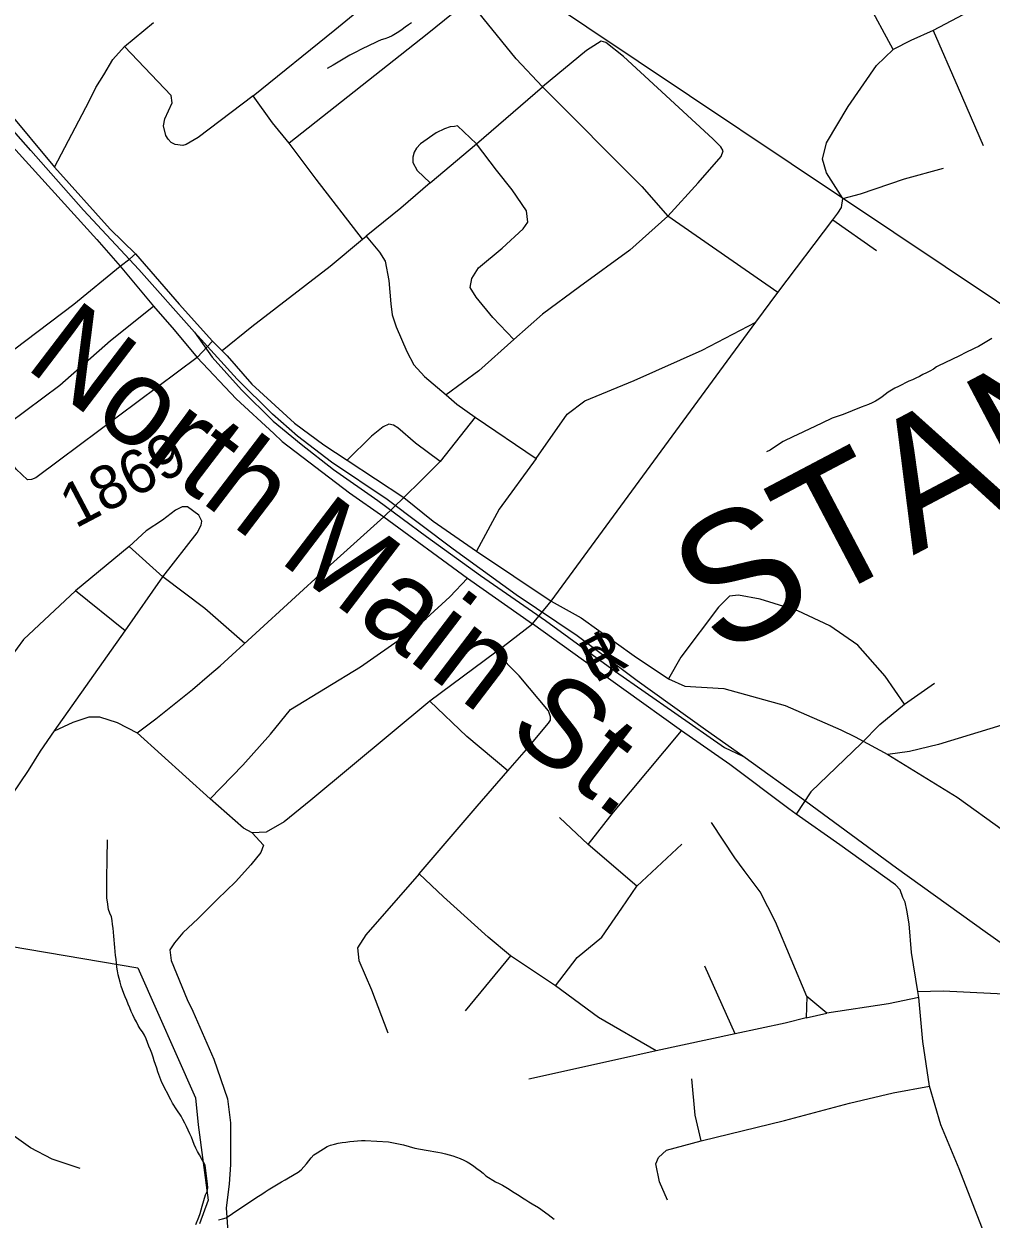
# Model space of a CAD drawing. Extents: x 1379448 to 1382868, y 593769 to 596827.
# Drawn here: x 1379666.4 to 1379829.3, y 595296.5 to 595497.8 of the extents above; entities that cross this region are included whole.
import ezdxf

# ---------------------------------------------------------------- set-up
doc = ezdxf.new("R2010")
doc.units = 0
for name, color, linetype in [('Old_Level_11', 7, 'Continuous'), ('Old_Level_29', 7, 'Continuous'), ('Old_Level_32', 7, 'Continuous'), ('Old_Level_35', 7, 'Continuous'), ('Old_Level_44', 7, 'Continuous'), ('Old_Level_48', 7, 'Continuous'), ('Old_Level_49', 7, 'Continuous'), ('Old_Level_62', 7, 'Continuous'), ('Old_Level_8', 7, 'Continuous'), ('Old_Level_9', 7, 'Continuous')]:
    doc.layers.add(name, color=color, linetype=linetype)

msp = doc.modelspace()

# ---------------------------------------------------------------- linework, layer by layer
at = {"layer": 'Old_Level_29'}
for p, q in [((1379753.4, 595398.34), (1379755.24, 595400.56)), ((1379752.06, 595396.73), (1379753.4, 595398.34))]:
    msp.add_line(p, q, dxfattribs=at)
for points in [[(1379640.12, 595529.74), (1379642.72, 595520.77), (1379644.96, 595513.08), (1379647.86, 595504.89), (1379654.08, 595493.55), (1379657.74, 595488.96), (1379663.5, 595483.3), (1379671.56, 595473.65)], [(1379671.56, 595473.65), (1379680.9, 595463.24), (1379685.19, 595459.06), (1379692.56, 595450.57), (1379698.13, 595444.33)], [(1379698.13, 595444.33), (1379700.64, 595441.89), (1379704.77, 595437.1), (1379711.95, 595430.52), (1379716.9, 595426.9), (1379720.82, 595424.32), (1379730.39, 595418.01)], [(1379730.39, 595418.01), (1379735.33, 595414.03), (1379742.61, 595408.99), (1379755.24, 595400.56)], [(1379755.24, 595400.56), (1379760.29, 595397.73), (1379769.18, 595391.34), (1379774.97, 595387.44), (1379777.73, 595386.22), (1379784.32, 595385.81), (1379794.62, 595382.96), (1379804.03, 595378.87), (1379806.45, 595377.67), (1379811.94, 595374.69)], [(1379831.52, 595285.14), (1379828.82, 595291.86), (1379827.76, 595295.11), (1379823.94, 595304.93), (1379820.88, 595312.34), (1379818.98, 595318.82), (1379817.85, 595326.38), (1379817.16, 595333.81), (1379817.01, 595334.82), (1379815.94, 595341.38), (1379815.54, 595346.18), (1379815.14, 595348.48), (1379814.85, 595349.85), (1379814.48, 595350.64), (1379813.99, 595351.9), (1379813.2, 595352.79), (1379803.84, 595359.48), (1379796.47, 595364.69), (1379795.25, 595365.55), (1379785.33, 595373.02), (1379777.19, 595378.71), (1379767.45, 595385.65), (1379752.06, 595396.73)], [(1379811.94, 595374.69), (1379823.59, 595367.52), (1379831.41, 595361.9), (1379838.57, 595356.89), (1379842.83, 595353.5), (1379846.88, 595350.52)]]:
    msp.add_lwpolyline(points, dxfattribs=at)
at = {"layer": 'Old_Level_32'}
for p, q in [((1379695.58, 595441.57), (1379698.13, 595444.33)), ((1379727, 595414.78), (1379730.39, 595418.01))]:
    msp.add_line(p, q, dxfattribs=at)
for points in [[(1379860.35, 595537.12), (1379859.21, 595532.1), (1379857.66, 595529.56), (1379852.97, 595521.73), (1379848.78, 595515.26), (1379847.74, 595513.74), (1379845.88, 595511.74), (1379840.23, 595507.84), (1379835.65, 595505.19), (1379819.59, 595496.7)], [(1379812.86, 595493.5), (1379808.42, 595501.66), (1379803.01, 595512.18)], [(1379671.56, 595473.65), (1379677.38, 595484.79), (1379678.48, 595487.05), (1379679.86, 595489.23), (1379681.35, 595491.78), (1379683.35, 595493.98), (1379688.24, 595498.01)], [(1379819.59, 595496.7), (1379815.8, 595494.97), (1379812.86, 595493.5)], [(1379819.59, 595496.7), (1379823.78, 595487.01), (1379827.98, 595477.32)], [(1379601.44, 595458.83), (1379604.66, 595459.48), (1379610.03, 595460.12), (1379613.93, 595460.7), (1379617.23, 595461.19), (1379619.97, 595462.11), (1379621.96, 595463.26), (1379624.23, 595464.88), (1379629.84, 595468.77), (1379636.24, 595473.41), (1379638.96, 595475.22), (1379642.2, 595477.66), (1379651.08, 595484.15), (1379653.96, 595485.47), (1379655.18, 595485.62), (1379656.4, 595485.42), (1379657.84, 595484.23), (1379663.4, 595478.33), (1379678.65, 595461.45), (1379682.59, 595456.98), (1379688.21, 595450.22), (1379691.72, 595446.24), (1379695.58, 595441.57)], [(1379695.58, 595441.57), (1379702.14, 595434.61), (1379708.47, 595428.8), (1379709.87, 595427.45), (1379721.23, 595418.78), (1379727, 595414.78)], [(1379647.93, 595344.33), (1379662.96, 595365.77), (1379667.13, 595372.04), (1379669.18, 595375.3), (1379671.51, 595378.71), (1379674.67, 595380.16), (1379677.4, 595381.04), (1379679.14, 595381.04), (1379682.08, 595380.13), (1379685.44, 595378.39), (1379688.63, 595380.74), (1379694.77, 595385.64), (1379697.63, 595388.12), (1379699.45, 595389.64), (1379717.45, 595406.15), (1379727, 595414.78)], [(1379727, 595414.78), (1379741.1, 595404.4), (1379752.06, 595396.73)], [(1379873.86, 595392.77), (1379845.53, 595383.99), (1379837.78, 595381.7), (1379820.5, 595376.43), (1379815.6, 595375.21), (1379811.94, 595374.69)], [(1379704.81, 595361.51), (1379706.75, 595359.44), (1379706.27, 595358.2), (1379704.61, 595356.13), (1379702.04, 595353.29), (1379698.98, 595350.35), (1379695.76, 595347.1), (1379693.13, 595344.66), (1379691.75, 595343.01), (1379690.99, 595341.84), (1379691.21, 595339.99), (1379693.86, 595333.44), (1379694.82, 595331.48), (1379698.35, 595323.42), (1379700.68, 595316.74), (1379701.17, 595312.69), (1379701.21, 595305.64), (1379700.95, 595302.32), (1379700.43, 595298.37), (1379700.82, 595293.55)]]:
    msp.add_lwpolyline(points, dxfattribs=at)
at = {"layer": 'Old_Level_35'}
for p, q in [((1379742.66, 595477.56), (1379753.75, 595487.17)), ((1379734.8, 595471.03), (1379742.66, 595477.56)), ((1379793.39, 595452.52), (1379774.85, 595465.41)), ((1379793.39, 595452.52), (1379802.68, 595464.81)), ((1379802.68, 595464.81), (1379810, 595459.63)), ((1379723.45, 595461.55), (1379724.06, 595462.06)), ((1379789.71, 595447.53), (1379793.39, 595452.52)), ((1379742.41, 595431.54), (1379736.49, 595424.09)), ((1379742.41, 595431.54), (1379752.66, 595424.59)), ((1379684.09, 595409.76), (1379675.08, 595402.29)), ((1379689.79, 595404.67), (1379684.09, 595409.76)), ((1379683.42, 595395.55), (1379689.79, 595404.67)), ((1379683.42, 595395.55), (1379675.08, 595402.29)), ((1379671.51, 595378.71), (1379683.42, 595395.55)), ((1379745.88, 595391.93), (1379752.06, 595396.73)), ((1379745.88, 595391.93), (1379734.79, 595383.69)), ((1379814.77, 595383.21), (1379819.82, 595386.72)), ((1379697.77, 595367.23), (1379685.44, 595378.39)), ((1379761.47, 595359.56), (1379756.59, 595364.08)), ((1379769.63, 595352.54), (1379761.47, 595359.56)), ((1379769.63, 595352.54), (1379777.22, 595359.6)), ((1379748.38, 595340.83), (1379740.7, 595331.52)), ((1379755.93, 595335.75), (1379748.38, 595340.83)), ((1379786.22, 595327.65), (1379781.13, 595339.06)), ((1379798.28, 595333.96), (1379798.2, 595330.34)), ((1379801.64, 595331.17), (1379798.28, 595333.96)), ((1379798.2, 595330.34), (1379801.64, 595331.17)), ((1379786.22, 595327.65), (1379772.92, 595324.81))]:
    msp.add_line(p, q, dxfattribs=at)
for points in [[(1379705.01, 595485.66), (1379718.78, 595496.77), (1379724.96, 595501.92), (1379727.36, 595504.29), (1379730.99, 595508), (1379731.9, 595510.79)], [(1379741.35, 595501.72), (1379734.34, 595496.06), (1379711.06, 595477.68)], [(1379753.75, 595487.17), (1379749.3, 595491.92), (1379741.35, 595501.72)], [(1379705.01, 595485.66), (1379695.71, 595478.67), (1379693.7, 595477.49), (1379693.17, 595477.31), (1379691.84, 595477.45), (1379691.2, 595477.84), (1379690.67, 595478.38), (1379690.27, 595478.99), (1379689.91, 595480.6), (1379690.13, 595481.78), (1379691.37, 595484.47), (1379691.19, 595485.72), (1379683.35, 595493.98)], [(1379774.85, 595465.41), (1379779.99, 595471.01), (1379783.88, 595475.45), (1379784.19, 595476.39), (1379783.78, 595477.06), (1379782.45, 595478.45), (1379767.38, 595492.29), (1379764.41, 595494.65), (1379763.65, 595494.9), (1379761.15, 595493.29), (1379753.75, 595487.17)], [(1379804.33, 595468.38), (1379801.62, 595472.71), (1379800.92, 595474.99), (1379801.6, 595477.76), (1379805.25, 595483.87), (1379810, 595490.81), (1379812.86, 595493.5)], [(1379711.06, 595477.68), (1379708.27, 595481.11), (1379705.01, 595485.66)], [(1379753.75, 595487.17), (1379770.47, 595470.42), (1379774.85, 595465.41)], [(1379742.66, 595477.56), (1379739.45, 595480.62), (1379738.9, 595480.53), (1379738.22, 595480.46), (1379737.22, 595480.13), (1379735.86, 595479.45), (1379733.21, 595477.59), (1379732.5, 595476.87), (1379732.14, 595476.16), (1379731.93, 595475.34), (1379731.93, 595474.44), (1379732.61, 595473.09), (1379734.8, 595471.03)], [(1379723.45, 595461.55), (1379715.61, 595471.64), (1379711.06, 595477.68)], [(1379748.94, 595444.65), (1379745.37, 595448.33), (1379742.57, 595451.76), (1379741.57, 595453.41), (1379741.82, 595454.88), (1379742.96, 595456.7), (1379746.93, 595460.03), (1379750.5, 595463.25), (1379751.29, 595464.37), (1379751.05, 595466.3), (1379748.64, 595469.84), (1379745.99, 595473.17), (1379742.66, 595477.56)], [(1379804.33, 595468.38), (1379807.34, 595469.16), (1379814.74, 595471.71), (1379821.29, 595473.47)], [(1379734.8, 595471.03), (1379729.86, 595466.74), (1379724.06, 595462.06)], [(1379802.68, 595464.81), (1379803.51, 595465.91), (1379804.12, 595466.84), (1379804.33, 595468.38)], [(1379774.85, 595465.41), (1379768.48, 595459.66), (1379759.99, 595453.49), (1379753.75, 595448.87), (1379748.94, 595444.65)], [(1379699.8, 595442.8), (1379704.78, 595446.83), (1379717.97, 595456.96), (1379723.45, 595461.55)], [(1379724.06, 595462.06), (1379726.28, 595459.36), (1379727.23, 595457.83), (1379727.86, 595454.57), (1379728.21, 595450.61), (1379728.4, 595448.8), (1379729.07, 595446.77), (1379730.88, 595442.59), (1379732.1, 595440.34), (1379733.89, 595438.37), (1379737.5, 595435.31)], [(1379682.59, 595456.98), (1379684.25, 595458.22), (1379685.19, 595459.06)], [(1379654.98, 595435.44), (1379658.55, 595438.31), (1379674.79, 595450.57), (1379682.59, 595456.98)], [(1379660.91, 595428.42), (1379672.44, 595436.96), (1379680.99, 595444.45), (1379688.21, 595450.22)], [(1379752.66, 595424.59), (1379757.91, 595432.05), (1379760.91, 595434.28), (1379769.21, 595437.71), (1379780.63, 595442.81), (1379789.71, 595447.53)], [(1379755.24, 595400.56), (1379784.85, 595440.99), (1379789.71, 595447.53)], [(1379748.94, 595444.65), (1379743, 595439.34), (1379737.5, 595435.31)], [(1379695.58, 595441.57), (1379672.38, 595424.29), (1379668.41, 595421.32), (1379667.66, 595421.03), (1379666.97, 595420.96), (1379665.08, 595422.79), (1379660.91, 595428.42)], [(1379737.5, 595435.31), (1379739.33, 595433.75), (1379742.41, 595431.54)], [(1379736.49, 595424.09), (1379732.36, 595427.18), (1379729.4, 595429.77), (1379728.65, 595430.22), (1379727.85, 595430.37), (1379726.92, 595429.94), (1379724.95, 595428.35), (1379720.82, 595424.32)], [(1379736.49, 595424.09), (1379733.36, 595420.95), (1379730.39, 595418.01)], [(1379752.66, 595424.59), (1379746.43, 595416.02), (1379742.61, 595408.99)], [(1379689.79, 595404.67), (1379695.57, 595412.08), (1379696.27, 595413.36), (1379696.35, 595414.04), (1379695.83, 595415.03), (1379693.93, 595416.42), (1379693.04, 595416.45), (1379691.91, 595415.85), (1379689.73, 595414.21), (1379686.98, 595412.4), (1379684.09, 595409.76)], [(1379703.59, 595393.43), (1379696.88, 595399.34), (1379689.79, 595404.67)], [(1379697.77, 595367.23), (1379703.25, 595372.93), (1379707.91, 595378.13), (1379711.31, 595382.31), (1379723.07, 595389.51), (1379730.53, 595394.7), (1379734.15, 595397.65), (1379738.12, 595401.26), (1379741.1, 595404.4)], [(1379675.08, 595402.29), (1379666.29, 595394.09), (1379664.16, 595391.18), (1379661.94, 595387.82), (1379659.2, 595384.44), (1379653.91, 595380.05), (1379648.21, 595374.83)], [(1379814.77, 595383.21), (1379811.51, 595387.93), (1379806.86, 595393.12), (1379802.17, 595396.41), (1379796.79, 595398.91), (1379790.43, 595400.91), (1379786.78, 595401.58), (1379785.27, 595401.37), (1379783.41, 595399.55), (1379777.08, 595391.09), (1379774.97, 595387.44)], [(1379747.89, 595371.99), (1379751.04, 595375.54), (1379754.79, 595380.01), (1379755.08, 595380.51), (1379755.08, 595381.05), (1379754.76, 595382.06), (1379749.81, 595387.99), (1379745.88, 595391.93)], [(1379734.79, 595383.69), (1379714.74, 595367.03), (1379710.21, 595363.37), (1379707.21, 595361.65), (1379704.81, 595361.51)], [(1379747.89, 595371.99), (1379740.99, 595377.75), (1379734.79, 595383.69)], [(1379807.51, 595376.62), (1379810.59, 595379.77), (1379814.77, 595383.21)], [(1379761.47, 595359.56), (1379765.72, 595365), (1379777.19, 595378.71)], [(1379807.51, 595376.62), (1379798.94, 595368.44), (1379796.47, 595364.69)], [(1379732.98, 595354.59), (1379742.75, 595366.02), (1379747.89, 595371.99)], [(1379704.81, 595361.51), (1379703.38, 595362.3), (1379697.77, 595367.23)], [(1379798.28, 595333.96), (1379793, 595346.53), (1379790.45, 595351.57), (1379787.72, 595355.2), (1379786.18, 595357.32), (1379782.23, 595363.28)], [(1379732.98, 595354.59), (1379723.97, 595344.35), (1379722.58, 595342.13), (1379722.83, 595340.02), (1379724.94, 595335.08), (1379727.67, 595327.85)], [(1379748.38, 595340.83), (1379744.59, 595343.93), (1379737.06, 595350.73), (1379732.98, 595354.59)], [(1379755.93, 595335.75), (1379759.62, 595340.54), (1379763.74, 595343.95), (1379767.1, 595348.83), (1379769.63, 595352.54)], [(1379675.87, 595304.96), (1379671.12, 595306.53), (1379667.48, 595308.48), (1379663.55, 595311.26), (1379660.04, 595314.27), (1379658.08, 595316.61), (1379654.56, 595321.51), (1379650.37, 595327.74), (1379648.04, 595331.86), (1379645.74, 595334.73), (1379644.12, 595336.83), (1379643.07, 595338.95)], [(1379772.92, 595324.81), (1379763.16, 595330.44), (1379755.93, 595335.75)], [(1379817.01, 595334.82), (1379821.25, 595334.9), (1379838.31, 595334.08)], [(1379817.16, 595333.81), (1379812.02, 595332.72), (1379801.64, 595331.17)], [(1379798.2, 595330.34), (1379794.64, 595329.44), (1379786.22, 595327.65)], [(1379772.92, 595324.81), (1379765.9, 595323.2), (1379751.47, 595320)], [(1379780.47, 595309.64), (1379779.46, 595313.97), (1379778.92, 595320.06)], [(1379780.47, 595309.64), (1379794.5, 595313.09), (1379805.48, 595316), (1379812.86, 595317.72), (1379818.98, 595318.82)], [(1379774.82, 595299.66), (1379773.46, 595302.73), (1379772.86, 595305.74), (1379773.28, 595306.85), (1379774.64, 595308.06), (1379780.47, 595309.64)]]:
    msp.add_lwpolyline(points, dxfattribs=at)
at = {"layer": 'Old_Level_44'}
for points in [[(1379695.13, 595445.89), (1379685.74, 595456.41), (1379676.42, 595466.42), (1379667.54, 595476.47), (1379660.67, 595484.12), (1379654.94, 595491.27), (1379650.64, 595498.97), (1379646.87, 595505.77), (1379643.83, 595511.85), (1379641.39, 595518.68), (1379639.1, 595527.19), (1379636.3, 595536.17), (1379633.32, 595542.29), (1379630.17, 595548.59), (1379625.58, 595555.06), (1379618.7, 595563.25), (1379611.83, 595570.02), (1379605.2, 595575.91), (1379601.02, 595578.91), (1379575.42, 595598.05), (1379574.2, 595599.03)], [(1379841.11, 595335.81), (1379828.36, 595344.82), (1379813.4, 595355.58), (1379798.11, 595366.81), (1379787.48, 595374.46), (1379781.24, 595378.85), (1379769.68, 595387.11), (1379759.62, 595394.69), (1379749.34, 595401.63), (1379738.71, 595409.28), (1379727.6, 595417.68), (1379718.19, 595423.97), (1379712.49, 595428.37), (1379708.24, 595432.05), (1379702.32, 595437.95), (1379695.13, 595445.89), (1379685.74, 595456.41), (1379676.42, 595466.42), (1379667.54, 595476.47), (1379654.49, 595491.18)], [(1379787.48, 595374.46), (1379781.24, 595378.85), (1379769.68, 595387.11), (1379759.62, 595394.69), (1379749.34, 595401.63), (1379738.71, 595409.28), (1379727.6, 595417.68), (1379718.19, 595423.97), (1379712.49, 595428.37), (1379708.24, 595432.05), (1379702.32, 595437.95), (1379695.13, 595445.89)], [(1379695.13, 595445.89), (1379698.07, 595441.63), (1379703.04, 595436.16), (1379708.38, 595430.87), (1379713.1, 595426.98), (1379718.55, 595422.72), (1379725.99, 595417.5), (1379734.23, 595411.42), (1379743.33, 595404.88), (1379754.28, 595397.3), (1379766.03, 595388.69), (1379776.05, 595381.72), (1379784.43, 595375.88), (1379787.48, 595374.46)], [(1379937.5, 595266.13), (1379929.48, 595271.61), (1379920.39, 595278.14), (1379909.32, 595286.12), (1379894, 595297.06), (1379881.57, 595305.96), (1379866.93, 595316.98), (1379852.79, 595327.16), (1379841.11, 595335.81), (1379828.36, 595344.82), (1379813.4, 595355.58), (1379798.11, 595366.81), (1379787.48, 595374.46)]]:
    msp.add_lwpolyline(points, dxfattribs=at)
at = {"layer": 'Old_Level_48'}
for points in [[(1379937.54, 595313.11), (1379935.68, 595324.14), (1379926.32, 595374.29), (1379931.87, 595375.52), (1379929.49, 595387.82), (1379937.84, 595389.12), (1379931.29, 595425.64), (1379904.13, 595417.61), (1379896.01, 595407.11), (1379890.61, 595410.69), (1379752.56, 595503.09), (1379773.98, 595520.53), (1379770.04, 595524.52), (1379756.34, 595545.51), (1379753.67, 595549.68), (1379728.08, 595528.98), (1379706.83, 595543.73)], [(1379612.24, 595337.59), (1379626.26, 595357.04), (1379633.97, 595352.54), (1379639.74, 595349.09), (1379642.88, 595346.96), (1379645.58, 595344.92), (1379645.12, 595343.08), (1379651.31, 595346.25), (1379654.76, 595343.98), (1379685.6, 595338.77), (1379695.29, 595316.9), (1379695.73, 595312.33), (1379697.4, 595299.65), (1379695.98, 595295.65)]]:
    msp.add_lwpolyline(points, dxfattribs=at)
at = {"layer": 'Old_Level_49'}
for points in [[(1379937.54, 595313.11), (1379935.68, 595324.14), (1379926.32, 595374.29), (1379931.87, 595375.52), (1379929.49, 595387.82), (1379937.84, 595389.12), (1379931.29, 595425.64), (1379904.13, 595417.61), (1379896.01, 595407.11), (1379890.61, 595410.69), (1379752.56, 595503.09), (1379773.98, 595520.53), (1379770.04, 595524.52), (1379756.34, 595545.51), (1379753.67, 595549.68), (1379728.08, 595528.98), (1379706.83, 595543.73)], [(1379612.24, 595337.59), (1379626.26, 595357.04), (1379633.97, 595352.54), (1379639.74, 595349.09), (1379642.88, 595346.96), (1379645.58, 595344.92), (1379645.12, 595343.08), (1379651.31, 595346.25), (1379654.76, 595343.98), (1379685.6, 595338.77), (1379695.29, 595316.9), (1379695.73, 595312.33), (1379697.4, 595299.65), (1379695.98, 595295.65)]]:
    msp.add_lwpolyline(points, dxfattribs=at)
at = {"layer": 'Old_Level_62'}
for points in [[(1379731.69, 595497.98), (1379731.15, 595497.61), (1379730.61, 595497.22), (1379730.09, 595496.82), (1379729.55, 595496.44), (1379728.99, 595496.11), (1379728.41, 595495.8), (1379727.81, 595495.51), (1379727.21, 595495.25), (1379726.58, 595495.09), (1379725.98, 595494.84), (1379725.39, 595494.56), (1379724.79, 595494.27), (1379724.2, 595493.99), (1379723.61, 595493.7), (1379723.02, 595493.4), (1379722.44, 595493.11), (1379721.85, 595492.81), (1379721.27, 595492.51), (1379719.6, 595491.5), (1379718.49, 595490.82), (1379717.46, 595490.26)], [(1379829.46, 595444.8), (1379828.91, 595444.44), (1379828.35, 595444.1), (1379827.77, 595443.78), (1379827.2, 595443.47), (1379826.61, 595443.17), (1379826.03, 595442.87), (1379825.44, 595442.58), (1379824.85, 595442.3), (1379824.26, 595442.01), (1379823.66, 595441.73), (1379823.07, 595441.45), (1379822.48, 595441.17), (1379821.88, 595440.89), (1379821.29, 595440.6), (1379820.7, 595440.31), (1379820.12, 595440.01), (1379819.61, 595439.61), (1379819.03, 595439.29), (1379818.45, 595439), (1379817.86, 595438.71), (1379817.26, 595438.42), (1379816.67, 595438.14), (1379816.08, 595437.86), (1379815.48, 595437.58), (1379814.89, 595437.3), (1379814.3, 595437.01), (1379813.72, 595436.72), (1379813.13, 595436.42), (1379812.55, 595436.11), (1379811.99, 595435.78), (1379811.47, 595435.37), (1379810.96, 595434.95), (1379810.44, 595434.55), (1379809.87, 595434.23), (1379809.28, 595433.95), (1379808.67, 595433.69), (1379808.07, 595433.44), (1379807.46, 595433.2), (1379804.4, 595431.98), (1379802.56, 595431.39), (1379800.79, 595430.56), (1379796.64, 595428.58), (1379796.05, 595428.3), (1379795.46, 595428.01), (1379794.87, 595427.72), (1379794.28, 595427.43), (1379793.19, 595426.71), (1379792.11, 595426.01), (1379791.51, 595425.7)], [(1379695.36, 595295.55), (1379695.83, 595296.78), (1379696.06, 595297.39), (1379696.27, 595298.01), (1379696.42, 595298.65), (1379696.96, 595300.53), (1379697.28, 595301.11), (1379697.36, 595301.73), (1379697.32, 595302.38), (1379696.93, 595305.55), (1379696.63, 595306.12), (1379696.31, 595306.69), (1379695.98, 595307.26), (1379695.65, 595307.84), (1379695.33, 595308.42), (1379695.05, 595309.02), (1379694.82, 595309.64), (1379694.59, 595310.25), (1379694.32, 595310.84), (1379694.04, 595311.44), (1379693.76, 595312.03), (1379693.47, 595312.62), (1379693.17, 595313.21), (1379692.87, 595313.79), (1379692.13, 595314.87), (1379691.44, 595315.96), (1379691.12, 595316.54), (1379689.64, 595319.47), (1379688.93, 595321.26), (1379688.76, 595321.9), (1379688.56, 595322.52), (1379688.35, 595323.14), (1379688.13, 595323.76), (1379687.91, 595324.38), (1379687.68, 595324.99), (1379687.45, 595325.61), (1379687.21, 595326.22), (1379686.95, 595326.82), (1379686.68, 595327.42), (1379686.34, 595327.99), (1379685.98, 595328.53), (1379685.64, 595329.09), (1379685.33, 595329.67), (1379685.03, 595330.26), (1379684.73, 595330.84), (1379684.45, 595331.44), (1379684.2, 595332.04), (1379683.94, 595332.65), (1379683.7, 595333.26), (1379683.46, 595333.87), (1379683.23, 595334.48), (1379683, 595335.1), (1379682.79, 595335.72), (1379682.58, 595336.34), (1379682.4, 595336.97), (1379682.25, 595337.61), (1379682.13, 595338.26), (1379682.04, 595338.91), (1379681.96, 595339.56), (1379681.9, 595340.22), (1379681.83, 595340.87), (1379681.77, 595341.52), (1379681.71, 595342.18), (1379681.65, 595342.83), (1379681.59, 595343.49), (1379681.53, 595344.14), (1379681.47, 595344.8), (1379681.39, 595345.45), (1379681.32, 595346.1), (1379681.23, 595346.75), (1379681.12, 595347.39), (1379680.87, 595348), (1379680.62, 595348.61), (1379680.44, 595349.88), (1379680.36, 595350.54), (1379680.34, 595351.19), (1379680.34, 595351.85), (1379680.35, 595352.51), (1379680.35, 595353.16), (1379680.35, 595353.82), (1379680.36, 595354.48), (1379680.37, 595355.13), (1379680.38, 595355.79), (1379680.39, 595356.44), (1379680.4, 595357.1), (1379680.42, 595357.76), (1379680.42, 595358.41), (1379680.44, 595359.07), (1379680.45, 595360.33)], [(1379699.18, 595296.35), (1379699.83, 595296.48), (1379700.45, 595296.69), (1379702.6, 595298.15), (1379705.91, 595300.29), (1379706.45, 595300.67), (1379707, 595301.03), (1379707.55, 595301.38), (1379708.11, 595301.73), (1379708.67, 595302.07), (1379709.23, 595302.41), (1379709.8, 595302.74), (1379710.37, 595303.07), (1379710.94, 595303.39), (1379712.59, 595304.37), (1379713.1, 595304.78), (1379713.56, 595305.25), (1379713.97, 595305.76), (1379714.38, 595306.29), (1379714.79, 595306.8), (1379715.25, 595307.26), (1379715.79, 595307.63), (1379717.45, 595308.68), (1379718.06, 595308.91), (1379718.7, 595309.1), (1379719.33, 595309.25), (1379719.98, 595309.36), (1379720.63, 595309.43), (1379721.29, 595309.5), (1379721.94, 595309.56), (1379722.6, 595309.62), (1379723.25, 595309.67), (1379723.9, 595309.71), (1379727.81, 595309.46), (1379730.36, 595308.94), (1379732.24, 595308.39), (1379734.16, 595308.07), (1379734.81, 595307.97), (1379735.46, 595307.86), (1379736.1, 595307.74), (1379736.75, 595307.61), (1379737.39, 595307.47), (1379738.02, 595307.3), (1379738.65, 595307.11), (1379739.27, 595306.9), (1379739.89, 595306.67), (1379740.49, 595306.4), (1379741.06, 595306.09), (1379741.62, 595305.74), (1379742.16, 595305.38), (1379742.7, 595304.99), (1379743.23, 595304.6), (1379743.75, 595304.2), (1379744.22, 595303.76), (1379745.84, 595302.72), (1379746.44, 595302.46), (1379747.02, 595302.16), (1379747.59, 595301.82), (1379748.15, 595301.48), (1379748.71, 595301.13), (1379749.26, 595300.77), (1379749.81, 595300.41), (1379750.36, 595300.05), (1379750.92, 595299.7), (1379751.46, 595299.35), (1379752.02, 595299.01), (1379753.09, 595298.38), (1379754.69, 595297.24), (1379755.22, 595296.86), (1379755.74, 595296.45)]]:
    msp.add_lwpolyline(points, dxfattribs=at)

# ---------------------------------------------------------------- texts
at = {"layer": 'Old_Level_11'}
msp.add_text('North Main St.', height=14.7638, rotation=322.6582, dxfattribs=at).set_placement((1379666.31, 595440.03))
at = {"layer": 'Old_Level_32'}
msp.add_text('VICINITY MAP SHOWING LOCATION OF PROJECT B-4118', height=18, rotation=27.7977, dxfattribs=at).set_placement((1379828.68, 595001.39))
at = {"layer": 'Old_Level_8'}
msp.add_text('1869', height=7.382, rotation=27.7977, dxfattribs=at).set_placement((1379675.05, 595412.72))
at = {"layer": 'Old_Level_9'}
for s, height, p in [('STANLEY', 21.653, (1379783.45, 595390.97)), ('R', 7.22, (1379762.61, 595386.64)), ('d', 7.22, (1379762.57, 595386.63))]:
    msp.add_text(s, height=height, rotation=27.7977, dxfattribs=at).set_placement(p)

doc.saveas('drawing.dxf')
